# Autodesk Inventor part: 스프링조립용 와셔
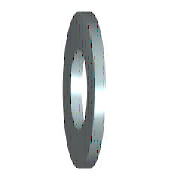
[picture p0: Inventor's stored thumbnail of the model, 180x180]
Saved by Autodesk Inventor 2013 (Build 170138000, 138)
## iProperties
IsCustomPart: 1
Created: 2012-02
Part Number: 스프링조립용 와셔
Material: 강철, 연강
Description: 평면 와셔
Document SubType Name: Modeling
Standard: KS B 1326
Designer: mduedu
Standards Organization: KS
Language: ko-KR
Size Designation: 12x24
Categories: <MemberInstance><Categories><Category DisplayName="조임쇠" InternalName="e4da775c-781d-43d5-af7c-5136215cf5a6" Mnemonic="FSTN"><Category DisplayName="와셔" InternalN
Density: 1 g/cm^3
Author: mduedu
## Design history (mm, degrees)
sketch "스케치"
  geometry: C1 r 12 at (0, 0); C2 r 7 at (0, 0); 1 further point
  constraints: 2 centre point, 2 coincident
  dimensions: "d0" = 14 diameter of C2 (= SD1); "d1" = 24 diameter of C1 (= SD2)
extrude "본체" new body sketch "스케치" distance "d2" = 2.3 (= SD); taper "d3" = 0 deg
workaxis "Work Axis1"
workplane "Work Plane1"
body "Solid1"
other parameters: "SD1" = 14 [user parameter; used in 1 equation term], "SD2" = 24 [user parameter; used in 1 equation term], "SD" = 2.3 [user parameter; used in 1 equation term], "d4" = 0, "d5" = 0, "d6" = 0, "d7" = 0, "NND" = 12 [user parameter]
